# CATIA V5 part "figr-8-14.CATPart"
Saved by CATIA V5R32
Part number: Part1
Bounding box of the stored display mesh (mm): x -13.793 to 92.338, y -14.211 to 51.229, z 54 to 123.392
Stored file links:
  D:\PROJECTS\Project 2022\CATIA V5 6R 2022\Resources\Part Files\c08_catia_v5_6r2022_prt\figr-8-14.CATPart
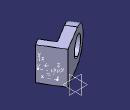
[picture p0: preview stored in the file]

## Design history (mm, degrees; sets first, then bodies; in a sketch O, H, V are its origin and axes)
AxisSystem1: origin (79.4802, 0.6447, 69), X (-0.515, 0.8572, 0), Y (0, 0, 1), Z (-0.8572, -0.515, 0)
AxisSystem2: origin (64.029, 26.3597, 54), X (0.515, -0.8572, 0), Y (-0.8572, -0.515, 0), Z (0, 0, 1)
Body1 (main body)
  Sketch1 on yz-plane, origin (0, 0, 0), H (0, 1, 0), V (0, 0, 1)
    point P1 (-104.4861, 0)
    line L1 (-104.4861, 0) -> (-104.4861, 44.267)
    arc A1 centre (-69.7903, 44.267) radius 34.6958 from (-104.4861, 44.267) to (-35.0946, 44.267) cw
    line L2 (-35.0946, 44.267) -> (-35.0946, 0)
    point P5 (-35.0946, 0)
    line L3 (-35.0946, 0) -> (-104.4861, 0)
    circle A2 centre (-69.7903, 44.267) radius 19.5413
    coincidence: P1 H, P5 H
    vertical: L1 V
    tangency: A1 L1, L2 A1
    horizontal: L3 H
  Pad1: profile Sketch1, direction (1, 0, 0), length 20
  Sketch2 on face of Pad1, origin (0, 0, 0), H (0, -1, 0), V (0, 0, 1)
    point P1 (35.0946, 0)
    line L1 (35.0946, 0) -> (104.4861, 0)
    line L2 (104.4861, 0) -> (104.4861, -15)
    line L3 (104.4861, -15) -> (35.0946, -15)
    line L4 (35.0946, -15) -> (35.0946, 0)
    reference projected line E1 (35.0946, 0) -> (35.0946, 44.267) from edge [face of Pad1 | face of Pad1]
    reference projected line E2 (104.4861, 44.267) -> (104.4861, 0) from edge [face of Pad1 | face of Pad1]
    distance L3 L1 = 15
    coincidence: P1 H, L4 E1, L2 E2
    horizontal: L1 H, L3 H
    vertical: L2 V, L4 V
  Pad2: profile Sketch2, direction (1, 0, 0), length 50
  Translate1: Direction xy-plane, ToTransfor Pad2, Length 69
  Rotate1: Axis edge, ToTransfor Translate1, Angle 121
  AxisToAxis1: AxisOrigin AxisSystem1, ToTransfor Rotate1, Axis AxisSystem2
